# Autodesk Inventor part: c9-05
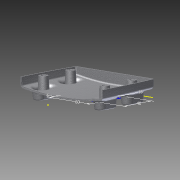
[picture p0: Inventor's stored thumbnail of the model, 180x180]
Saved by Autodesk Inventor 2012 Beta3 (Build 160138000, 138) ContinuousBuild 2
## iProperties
Created: 2010-12
Part Number: c9-05
Material: Default
Document SubType Name: Modeling
Designer: Beta-8540w
Density: 1 g/cm^3
Author: Beta-8540w
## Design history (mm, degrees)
sketch "Sketch1"
  geometry: L1 (-60, -12)-(60, -12); L2 (60, -12)-(60, 12); L3 (60, 12)-(-60, 12); L4 (-60, 12)-(-60, -12); A1 r 350 centre (0, -332.819) between (60, 12) and (-60, 12); A2 r 350 centre (0, 332.819) between (-60, -12) and (60, -12); 3 further points
  constraints: 8 end point, 4 point on circle, 2 centre point, 2 midpoint, 2 parallel, 1 equal radius, 1 horizontal, 1 horizontal alignment, 1 perpendicular, 1 vertical alignment
  dimensions: "d0" = 120 distance of L3.end L2.end; "d1" = 24 distance of L2.end L1.end; "d2" = 350 radius of A1
workplane "Work Plane4"
sketch "Sketch5"
  geometry: L1 (-60, 12)-(-60, -12) reference; L2 (60, -12)-(60, 12) reference; L3 (-58, 10.314)-(-58, -10.314); L4 (58, -10.314)-(58, 10.314); A1 r 350 centre (0, 332.819) between (-60, -12) and (60, -12) reference; A2 r 350 centre (0, -332.819) between (60, 12) and (-60, 12) reference; A3 r 348 centre (0, 332.819) between (-58, -10.314) and (58, -10.314); A4 r 348 centre (0, -332.819) between (58, 10.314) and (-58, 10.314); 1 further point
  constraints: 4 end point, 4 point on circle, 2 centre point, 3 other
  dimensions: "d37" = 2 distance between parallel lines of L2 L4
sketch "Sketch6"
  geometry: L1 (-60, 0)-(60, 0); L2 (60, 0)-(58.843, 22.085); L3 (-60, 0)-(-58.779, 23.307); A1 r 691.758 centre (630.81, -36.204) between (-60, 0) and (-58, -100); A2 r 691.758 centre (-630.81, -36.204) between (58, -100) and (60, 0); 1 further point
  constraints: 6 end point, 4 point on circle, 2 centre point, 2 tangent, 1 horizontal
  dimensions: "d53" = 87 deg angle of L1 L3; "d54" = 87 deg angle of L1 L2 (= d53)
sketch "Sketch7"
  geometry: L1 (17.181, 0)-(12, 0) reference; L2 (15.181, -100)-(10.314, -100) reference; L3 (17.181, 0)-(16.768, 11.838); A1 r 911.322 centre (-893.585, -31.805) between (15.181, -100) and (17.181, 0); 1 further point
  constraints: 2 end point, 2 point on circle, 1 centre point, 1 tangent
  dimensions: "d56" = 88 deg angle of L1 L3
feature "LoftSrf2" sketch "Sketch5", "Sketch6", "Sketch7" dims "d57" = 0, "d58" = 90 deg, "d59" = 0, "d60" = 90 deg, "d61" = 0, "d62" = 90 deg, "d63" = 0, "d64" = 90 deg, "d65" = 0, "d66" = 90 deg
sketch "Sketch2"
  geometry: L1 (-75, -16)-(75, -16); L2 (-75, -60)-(75, -60); A1 r 183.781 centre (0, -183.781) between (75, -16) and (-75, -16); 2 further points
  constraints: 4 end point, 3 point on circle, 1 centre point, 1 coincident, 1 horizontal, 1 parallel
  dimensions: "d5" = 16 distance from line of point (0, 0) L1; "d7" = 60 distance from line of point (0, 0) L2; "d55" = 150 distance of L1.start L1.end
feature "RevolutionSrf1" sketch "Sketch2" dims angle "d8" = 40 deg
patch "Boundary Patch1" dims "d13" = 0, "d67" = 0, "d68" = 0, "d69" = 0, "d70" = 0
workplane "Work Plane1"
sketch "Sketch3"
  geometry: L1 (52, -85)-(52, -73); L2 (38, -73)-(38, -85); A1 r 7 centre (45, -73) between (52, -73) and (38, -73); A2 r 7 centre (45, -85) between (38, -85) and (52, -85); 1 further point
  constraints: 4 end point, 4 point on circle, 4 tangent, 2 centre point, 1 parallel, 1 vertical
  dimensions: "d15" = 12 distance of L1.start L1.end; "d16" = 7 radius of A1; "d50" = 45 horizontal distance of A1.centre point (0, 0); "d51" = 85 vertical distance of point (0, 0) A2.centre
extrude_surface "ExtrusionSrf2" sketch "Sketch3" dims "d19" = 14, "d20" = 5 deg
pattern_linear "Rectangular Pattern1" dims "d23" = 90
workplane "Work Plane2"
feature "Sculpt1"
sketch "Sketch4"
  geometry: L1 (-24.5, 6)-(24.5, 6); L2 (27.5, 3)-(27.5, -3); L3 (24.5, -6)-(-24.5, -6); L4 (-27.5, -3)-(-27.5, 3); A1 r 3 centre (-24.5, 3) between (-24.5, 6) and (-27.5, 3); A2 r 3 centre (24.5, 3) between (27.5, 3) and (24.5, 6); A3 r 3 centre (24.5, -3) between (24.5, -6) and (27.5, -3); A4 r 3 centre (-24.5, -3) between (-27.5, -3) and (-24.5, -6); 6 further points
  constraints: 8 end point, 8 point on circle, 8 tangent, 6 point on line, 4 centre point, 3 equal radius, 2 midpoint, 2 parallel, 1 horizontal, 1 horizontal alignment, 1 perpendicular, 1 vertical alignment
  dimensions: "d28" = 55 distance of point (27.5, -6) point (-27.5, -6); "d29" = 12 distance of point (27.5, 6) point (27.5, -6); "d30" = 3 radius of A1
extrude_surface "ExtrusionSrf6" sketch "Sketch4" dims "d31" = 14, "d32" = 45 deg
patch "Boundary Patch2" dims "d33" = 0, "d34" = 0
fillet "Fillet1" dims "d79" = 4, "d80" = 3, "d81" = 1
feature "Sculpt2"
node "Splitting Plane 1"
shell "Shell1" dims "d83" = 2
split "Split1"
  body "Solid1"
feature "Lip1" dims "d142" = 1, "d143" = 1, "d144" = 0, "d145" = 0, "d146" = 0, "d147" = 0
feature "Lip2" dims "d148" = 1, "d149" = 1, "d150" = 0, "d151" = 0, "d152" = 0, "d153" = 0.5
split "Split3"
  node "Back"
sketch "Sketch9"
  geometry: L1 (50.167, -73)-(50.167, -85) reference; L2 (39.833, -85)-(39.833, -73) reference; L3 (45, -73)-(45, -85); L4 (45, -85)-(39.833, -85); A1 r 5.167 centre (45, -73) between (50.167, -73) and (39.833, -73) reference; A2 r 5.167 centre (45, -85) between (39.833, -85) and (50.167, -85) reference; 5 further points
  constraints: 4 end point, 1 horizontal, 1 midpoint, 1 parallel, 1 perpendicular, 1 vertical, 3 other
  dimensions: "d86" = 90 distance of point (45, -79) point (-45, -79); "d89" = 40 distance of point (45, -79) point (45, -39)
  node "Projected Loop1"
feature "Boss1" dims "d92" = 0, "d93" = 0, "d94" = 7, "d95" = 2, "d96" = 0.5, "d97" = 6, "d98" = 1.25, "d99" = 3.5, "d100" = 2.5 deg, "d101" = 2.5 deg, "d102" = 2.5 deg, "d103" = 2.5 deg, "d104" = 90 deg, "d107" = 2, "d108" = 2, "d109" = 10, "d110" = 0, "d111" = 10 deg, "d112" = 2.5 deg, "d113" = 0, "d114" = 0, "d115" = 0, "d116" = 360 deg
feature "Boss2" dims "d117" = 3, "d118" = 0, "d119" = 6, "d120" = 3, "d121" = 9.5, "d122" = 2 deg, "d123" = 1 deg, "d126" = 2, "d127" = 2, "d128" = 10, "d129" = 0, "d130" = 10 deg, "d131" = 2.5 deg, "d132" = 0, "d133" = 0, "d134" = 0, "d135" = 360 deg
workplane "Work Plane6"
sketch "Sketch10"
  geometry: L1 (24, -85)-(-24, -85); L2 (-30, -79)-(-30, -51); L3 (-24, -45)-(24, -45); L4 (30, -51)-(30, -79); L5 (54.344, -100)-(-54.344, -100) reference; A1 r 6 centre (-24, -51) between (-24, -45) and (-30, -51); A2 r 6 centre (24, -51) between (30, -51) and (24, -45); A3 r 6 centre (24, -79) between (24, -85) and (30, -79); A4 r 6 centre (-24, -79) between (-30, -79) and (-24, -85); 5 further points
  constraints: 8 end point, 8 point on circle, 8 tangent, 6 point on line, 4 centre point, 3 equal radius, 2 parallel, 1 horizontal, 1 midpoint, 1 perpendicular, 1 vertical alignment
  dimensions: "d137" = 60 distance of point (-30, -45) point (30, -45); "d138" = 40 distance of point (-30, -85) point (-30, -45); "d139" = 15 distance between parallel lines of L5 L1; "d141" = 6 radius of A2
body "Srf2"
body "Srf3"
body "Srf4"
body "Srf5"
body "Srf6"
body "Srf7"
body "Srf8"
body "Srf9"
body "Srf11"
feature "Stitch Surface1"
body "Srf12"
extrude_surface "ExtrusionSrf3"
extrude_surface "ExtrusionSrf4"
extrude_surface "ExtrusionSrf5"
node "Front"
node "Back - Top"
node "Back - Bottom"
other parameters: "d14" = -24, "d52" = -6
